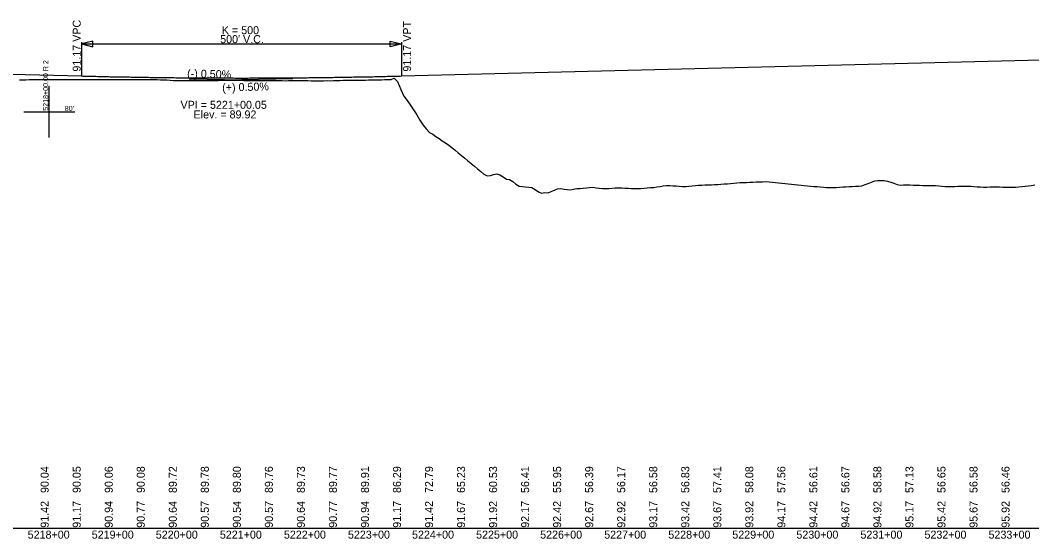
# Model space of a CAD drawing. Extents: x 2147288 to 2220488, y 740833 to 759333.
# Drawn here: x 2154136 to 2155715, y 742067 to 742876 of the extents above; entities that cross this region are included whole.
import ezdxf

# ---------------------------------------------------------------- set-up
doc = ezdxf.new("R2010")
doc.units = 0
for name, color, linetype in [('RD_DDB_GradeTX', 7, 'Continuous'), ('RD_DDB_Profile_EX', 7, 'Continuous'), ('RD_DDB_Profile_Lbl', 7, 'Continuous'), ('RD_DDB_Profile_PR', 7, 'Continuous'), ('RD_DDB_StaTX', 7, 'Continuous'), ('RD_DDB_StripGrade', 7, 'Continuous'), ('RD_DDB_VCLbl', 7, 'Continuous'), ('RD_GPK_Profile_Cell', 7, 'Continuous')]:
    doc.layers.add(name, color=color, linetype=linetype)

msp = doc.modelspace()

# ---------------------------------------------------------------- linework, layer by layer
at = {"layer": 'RD_DDB_GradeTX'}
for p in [(2154401.2, 742785), (2154561.1, 742785)]:
    msp.add_line(p, (2154481.1, 742783), dxfattribs=at)
at = {"layer": 'RD_DDB_Profile_EX'}
for points in [[(2154134.6, 742783.5), (2154139.6, 742783.5), (2154144.6, 742783.5), (2154149.6, 742783.6), (2154154.6, 742783.6), (2154159.6, 742783.6), (2154164.6, 742783.6), (2154169.6, 742783.6), (2154174.6, 742783.6), (2154179.6, 742783.6), (2154184.6, 742783.6), (2154189.6, 742783.6), (2154194.6, 742783.6), (2154199.6, 742783.6), (2154204.6, 742783.7), (2154209.6, 742783.7), (2154214.6, 742783.7), (2154219.6, 742783.7), (2154224.6, 742783.7), (2154229.6, 742783.7), (2154234.6, 742783.7), (2154239.6, 742783.7), (2154244.6, 742783.7), (2154249.6, 742783.8), (2154254.6, 742783.8), (2154259.6, 742783.8), (2154264.6, 742783.8), (2154269.6, 742783.8), (2154274.6, 742783.7), (2154279.6, 742783.7), (2154284.6, 742783.7), (2154289.6, 742783.7), (2154294.6, 742783.8), (2154299.6, 742783.8), (2154304.6, 742783.8), (2154309.6, 742783.8), (2154314.6, 742783.8), (2154319.6, 742783.9), (2154324.6, 742783.8), (2154329.6, 742783.8), (2154334.6, 742783.8), (2154339.6, 742783.9), (2154344.6, 742783.9), (2154349.6, 742783.9), (2154354.6, 742783.2), (2154359.6, 742783.2), (2154364.6, 742783), (2154369.6, 742782.7), (2154374.6, 742782.4), (2154379.6, 742782), (2154384.6, 742782.1), (2154389.6, 742782.1), (2154394.6, 742782), (2154399.6, 742782), (2154404.6, 742782.1), (2154409.6, 742782.1), (2154414.6, 742782.1), (2154419.6, 742782.1), (2154424.6, 742782.3), (2154429.6, 742782.3), (2154434.6, 742782.3), (2154439.6, 742782.3), (2154444.6, 742782.4), (2154449.6, 742782.5), (2154454.6, 742782.6), (2154459.6, 742782.7), (2154464.6, 742782.7), (2154469.6, 742782.6), (2154474.6, 742782.6), (2154479.6, 742782.5), (2154484.6, 742782.4), (2154489.6, 742782.3), (2154494.6, 742782.3), (2154499.6, 742782.3), (2154504.6, 742782.3), (2154509.6, 742782.3), (2154514.6, 742782.2), (2154519.6, 742782.2), (2154524.6, 742782.2), (2154529.6, 742782.2), (2154534.6, 742782.3)], [(2154534.6, 742782.3), (2154539.6, 742782.2), (2154544.6, 742782), (2154549.6, 742781.9), (2154554.6, 742782), (2154559.6, 742782.1), (2154564.6, 742782), (2154569.6, 742782), (2154574.6, 742782), (2154579.6, 742782.1), (2154584.6, 742782), (2154589.6, 742781.9), (2154594.6, 742781.8), (2154599.6, 742781.8), (2154604.6, 742781.9), (2154609.6, 742781.9), (2154614.6, 742782), (2154619.6, 742781.9), (2154624.6, 742782), (2154629.6, 742782.2), (2154634.6, 742782.4), (2154639.6, 742782.6), (2154644.6, 742782.8), (2154649.6, 742782.9), (2154654.6, 742782.9), (2154659.6, 742782.9), (2154664.6, 742782.9), (2154669.6, 742782.9), (2154674.6, 742782.9), (2154679.6, 742783), (2154684.6, 742783), (2154689.6, 742783), (2154694.6, 742783.1), (2154699.6, 742783.3), (2154704.6, 742783.6), (2154709.6, 742783.7), (2154714.6, 742783.9), (2154719.6, 742786), (2154724.6, 742780.7), (2154729.6, 742768), (2154734.6, 742757.6), (2154739.6, 742750.9), (2154744.6, 742744.1), (2154749.6, 742736.5), (2154754.6, 742728.5), (2154759.6, 742720.5), (2154764.6, 742712.5), (2154769.6, 742706.6), (2154774.6, 742700.9), (2154779.6, 742698.4), (2154784.6, 742695), (2154789.6, 742691.6), (2154794.6, 742688.3), (2154799.6, 742684.9), (2154804.6, 742681.5), (2154809.6, 742677.4), (2154814.6, 742673.3), (2154819.6, 742669.1), (2154824.6, 742665), (2154829.6, 742660.8), (2154834.6, 742656.7), (2154839.6, 742652.6), (2154844.6, 742648.4), (2154849.6, 742644.3), (2154854.6, 742640.1), (2154859.6, 742636), (2154864.6, 742633.5), (2154869.6, 742633.9), (2154874.6, 742635.5), (2154879.6, 742636.5), (2154884.6, 742635.2), (2154889.6, 742631.7), (2154894.6, 742628.3), (2154899.6, 742627.6), (2154904.6, 742624.5), (2154909.6, 742620.5), (2154914.6, 742617.3), (2154919.6, 742616.6), (2154924.6, 742616), (2154929.6, 742615.6), (2154934.6, 742615.1), (2154939.6, 742611.9), (2154944.6, 742608.6), (2154949.6, 742606.6), (2154954.6, 742607.2), (2154959.6, 742606.9), (2154964.6, 742608.9), (2154969.6, 742611.1), (2154974.6, 742613.1), (2154979.6, 742613.4), (2154984.6, 742612.7), (2154989.6, 742611.9), (2154994.6, 742611.8), (2154999.6, 742612.7), (2155004.6, 742613.5), (2155009.6, 742613.8), (2155014.6, 742614.4), (2155019.6, 742614.9), (2155024.6, 742615.4), (2155029.6, 742615.6), (2155034.6, 742614.9)], [(2155034.6, 742614.9), (2155039.6, 742614.2), (2155044.6, 742613.6), (2155049.6, 742613.7), (2155054.6, 742613.9), (2155059.6, 742614.2), (2155064.6, 742614.5), (2155069.6, 742614.6), (2155074.6, 742614.6), (2155079.6, 742614.4), (2155084.6, 742614.1), (2155089.6, 742613.9), (2155094.6, 742613.8), (2155099.6, 742613.6), (2155104.6, 742613.9), (2155109.6, 742614.3), (2155114.6, 742614.7), (2155119.6, 742615), (2155124.6, 742615.3), (2155129.6, 742616.1), (2155134.6, 742616.9), (2155139.6, 742617.7), (2155144.6, 742618.2), (2155149.6, 742618.4), (2155154.6, 742618), (2155159.6, 742617.6), (2155164.6, 742617.3), (2155169.6, 742617), (2155174.6, 742617), (2155179.6, 742617.4), (2155184.6, 742617.9), (2155189.6, 742618.4), (2155194.6, 742618.8), (2155199.6, 742619), (2155204.6, 742619.2), (2155209.6, 742619.3), (2155214.6, 742619.6), (2155219.6, 742619.8), (2155224.6, 742620.1), (2155229.6, 742620.4), (2155234.6, 742620.7), (2155239.6, 742620.9), (2155244.6, 742621.3), (2155249.6, 742621.8), (2155254.6, 742622.3), (2155259.6, 742622.8), (2155264.6, 742623), (2155269.6, 742623.2), (2155274.6, 742623.5), (2155279.6, 742623.8), (2155284.6, 742624), (2155289.6, 742624.1), (2155294.6, 742624.3), (2155299.6, 742624.4), (2155304.6, 742624.3), (2155309.6, 742623.7), (2155314.6, 742623), (2155319.6, 742622.4), (2155324.6, 742621.9), (2155329.6, 742621.4), (2155334.6, 742620.9), (2155339.6, 742620.4), (2155344.6, 742619.9), (2155349.6, 742619.4), (2155354.6, 742618.9), (2155359.6, 742618.4), (2155364.6, 742617.9), (2155369.6, 742617.5), (2155374.6, 742617), (2155379.6, 742616.6), (2155384.6, 742616.2), (2155389.6, 742615.8), (2155394.6, 742615.4), (2155399.6, 742615.1), (2155404.6, 742615.2), (2155409.6, 742615.4), (2155414.6, 742615.6), (2155419.6, 742616), (2155424.6, 742616.3), (2155429.6, 742616.7), (2155434.6, 742617), (2155439.6, 742617.2), (2155444.6, 742617.4), (2155449.6, 742617.8), (2155454.6, 742619.7), (2155459.6, 742621.6), (2155464.6, 742623.6), (2155469.6, 742625.5), (2155474.6, 742626.2), (2155479.6, 742626.3), (2155484.6, 742626.4), (2155489.6, 742625.2), (2155494.6, 742623.5), (2155499.6, 742621.8), (2155504.6, 742620.1), (2155509.6, 742619.1), (2155514.6, 742619.2), (2155519.6, 742619.4), (2155524.6, 742619.4), (2155529.6, 742619.1), (2155534.6, 742618.9)], [(2155534.6, 742618.9), (2155539.6, 742618.6), (2155544.6, 742618.4), (2155549.6, 742618.3), (2155554.6, 742618.2), (2155559.6, 742618.1), (2155564.6, 742618.1), (2155569.6, 742617.7), (2155574.6, 742617.2), (2155579.6, 742616.7), (2155584.6, 742616.6), (2155589.6, 742616.8), (2155594.6, 742616.9), (2155599.6, 742617.1), (2155604.6, 742617.2), (2155609.6, 742617.3), (2155614.6, 742617.4), (2155619.6, 742617.4), (2155624.6, 742616.9), (2155629.6, 742616.5), (2155634.6, 742616), (2155639.6, 742615.6), (2155644.6, 742615.7), (2155649.6, 742616), (2155654.6, 742616.2), (2155659.6, 742616.1), (2155664.6, 742616), (2155669.6, 742615.9), (2155674.6, 742615.8), (2155679.6, 742615.8), (2155684.6, 742615.7), (2155689.6, 742615.6), (2155694.6, 742616), (2155699.6, 742616.6), (2155704.6, 742617.2), (2155709.6, 742617.8), (2155714.6, 742618.5), (2155719.6, 742619.4)]]:
    msp.add_lwpolyline(points, dxfattribs=at)
at = {"layer": 'RD_DDB_Profile_PR'}
for p, q in [((2154731.1, 742789.3), (2156331.1, 742829.3)), ((2154061.1, 742793.5), (2154231.1, 742789.3))]:
    msp.add_line(p, q, dxfattribs=at)
msp.add_spline([(2154231.1, 742789.3), (2154241.1, 742789), (2154251.1, 742788.8), (2154261.1, 742788.6), (2154271.1, 742788.3), (2154281.1, 742788.1), (2154291.1, 742787.9), (2154301.1, 742787.8), (2154311.1, 742787.6), (2154321.1, 742787.4), (2154331.1, 742787.3), (2154341.1, 742787.1), (2154351.1, 742787), (2154361.1, 742786.9), (2154371.1, 742786.7), (2154381.1, 742786.6), (2154391.1, 742786.5), (2154401.1, 742786.5), (2154411.1, 742786.4), (2154421.1, 742786.3), (2154431.1, 742786.3), (2154441.1, 742786.2), (2154451.1, 742786.2), (2154461.1, 742786.2), (2154471.1, 742786.1), (2154481.1, 742786.1), (2154491.1, 742786.1), (2154501.1, 742786.2), (2154511.1, 742786.2), (2154521.1, 742786.2), (2154531.1, 742786.3), (2154541.1, 742786.3), (2154551.1, 742786.4), (2154561.1, 742786.5), (2154571.1, 742786.5), (2154581.1, 742786.6), (2154591.1, 742786.7), (2154601.1, 742786.9), (2154611.1, 742787), (2154621.1, 742787.1), (2154631.1, 742787.3), (2154641.1, 742787.4), (2154651.1, 742787.6), (2154661.1, 742787.8), (2154671.1, 742787.9), (2154681.1, 742788.1), (2154691.1, 742788.3), (2154701.1, 742788.6), (2154711.1, 742788.8), (2154721.1, 742789), (2154731.1, 742789.3)], degree=3, dxfattribs=at)
at = {"layer": 'RD_DDB_VCLbl'}
for p, q in [((2154231.1, 742841.8), (2154231.1, 742789.3)), ((2154231.1, 742839.3), (2154731.1, 742839.3)), ((2154731.1, 742841.8), (2154731.1, 742789.3))]:
    msp.add_line(p, q, dxfattribs=at)
for points in [[(2154249.1, 742843.8), (2154231.1, 742839.3), (2154249.1, 742834.8)], [(2154713.1, 742843.8), (2154731.1, 742839.3), (2154713.1, 742834.8)]]:
    msp.add_lwpolyline(points, close=True, dxfattribs=at)
at = {"layer": 'RD_GPK_Profile_Cell'}
for p, q in [((2154181.1, 742693.4), (2154181.1, 742773.4)), ((2154141.1, 742733.4), (2154221.1, 742733.4)), ((2148888.3, 742083.4), (2165888.3, 742083.4))]:
    msp.add_line(p, q, dxfattribs=at)

# ---------------------------------------------------------------- texts
at = {"layer": 'RD_DDB_GradeTX'}
for s, rotation, p in [('(-) 0.50%', 358.5679, (2154396.1, 742787.1)), ('(+) 0.50%', 1.4321, (2154451.1, 742765))]:
    msp.add_text(s, height=12.5, rotation=rotation, dxfattribs=at).set_placement(p)
at = {"layer": 'RD_DDB_Profile_Lbl'}
for s, p in [('VPI = 5221+00.05', (2154385.9, 742738)), ('Elev. = 89.92', (2154406.3, 742723))]:
    msp.add_text(s, height=12.5, dxfattribs=at).set_placement(p)
at = {"layer": 'RD_DDB_StaTX'}
for s, p in [('5218+00', (2154147.3, 742067.2)), ('5219+00', (2154247.3, 742067.2)), ('5220+00', (2154347.3, 742067.2)), ('5221+00', (2154447.3, 742067.2)), ('5222+00', (2154547.3, 742067.2)), ('5223+00', (2154647.3, 742067.2)), ('5224+00', (2154747.3, 742067.2)), ('5225+00', (2154847.3, 742067.2)), ('5226+00', (2154947.3, 742067.2)), ('5227+00', (2155047.3, 742067.2)), ('5228+00', (2155147.3, 742067.2)), ('5229+00', (2155247.3, 742067.2)), ('5230+00', (2155347.3, 742067.2)), ('5231+00', (2155447.3, 742067.2)), ('5232+00', (2155547.3, 742067.2)), ('5233+00', (2155647.3, 742067.2))]:
    msp.add_text(s, height=12.5, dxfattribs=at).set_placement(p)
at = {"layer": 'RD_DDB_StripGrade'}
for s, p in [('91.17 VPC', (2154230.1, 742796.1)), ('91.17 VPT', (2154745.8, 742796.1)), ('90.04', (2154180.1, 742138.4)), ('90.05', (2154230.1, 742138.4)), ('90.06', (2154280.1, 742138.4)), ('90.08', (2154330.1, 742138.4)), ('89.72', (2154380.1, 742138.4)), ('89.78', (2154430.1, 742138.4)), ('89.80', (2154480.1, 742138.4)), ('89.76', (2154530.1, 742138.4)), ('89.73', (2154580.1, 742138.4)), ('89.77', (2154630.1, 742138.4)), ('89.91', (2154680.1, 742138.4)), ('86.29', (2154730.1, 742138.4)), ('72.79', (2154780.1, 742138.4)), ('65.23', (2154830.1, 742138.4)), ('60.53', (2154880.1, 742138.4)), ('56.41', (2154930.1, 742138.4)), ('55.95', (2154980.1, 742138.4)), ('56.39', (2155030.1, 742138.4)), ('56.17', (2155080.1, 742138.4)), ('56.58', (2155130.1, 742138.4)), ('56.83', (2155180.1, 742138.4)), ('57.41', (2155230.1, 742138.4)), ('58.08', (2155280.1, 742138.4)), ('57.56', (2155330.1, 742138.4)), ('56.61', (2155380.1, 742138.4)), ('56.67', (2155430.1, 742138.4)), ('58.58', (2155480.1, 742138.4)), ('57.13', (2155530.1, 742138.4)), ('56.65', (2155580.1, 742138.4)), ('56.58', (2155630.1, 742138.4)), ('56.46', (2155680.1, 742138.4)), ('91.42', (2154180.1, 742084.2)), ('91.17', (2154230.1, 742084.2)), ('90.94', (2154280.1, 742084.2)), ('90.77', (2154330.1, 742084.2)), ('90.64', (2154380.1, 742084.2)), ('90.57', (2154430.1, 742084.2)), ('90.54', (2154480.1, 742084.2)), ('90.57', (2154530.1, 742084.2)), ('90.64', (2154580.1, 742084.2)), ('90.77', (2154630.1, 742084.2)), ('90.94', (2154680.1, 742084.2)), ('91.17', (2154730.1, 742084.2)), ('91.42', (2154780.1, 742084.2)), ('91.67', (2154830.1, 742084.2)), ('91.92', (2154880.1, 742084.2)), ('92.17', (2154930.1, 742084.2)), ('92.42', (2154980.1, 742084.2)), ('92.67', (2155030.1, 742084.2)), ('92.92', (2155080.1, 742084.2)), ('93.17', (2155130.1, 742084.2)), ('93.42', (2155180.1, 742084.2)), ('93.67', (2155230.1, 742084.2)), ('93.92', (2155280.1, 742084.2)), ('94.17', (2155330.1, 742084.2)), ('94.42', (2155380.1, 742084.2)), ('94.67', (2155430.1, 742084.2)), ('94.92', (2155480.1, 742084.2)), ('95.17', (2155530.1, 742084.2)), ('95.42', (2155580.1, 742084.2)), ('95.67', (2155630.1, 742084.2)), ('95.92', (2155680.1, 742084.2))]:
    msp.add_text(s, height=12.5, rotation=90, dxfattribs=at).set_placement(p)
at = {"layer": 'RD_DDB_VCLbl'}
for s, p in [('K = 500', (2154450.4, 742854.5)), ("500' V.C.", (2154447.8, 742840.5))]:
    msp.add_text(s, height=12.5, dxfattribs=at).set_placement(p)
at = {"layer": 'RD_GPK_Profile_Cell'}
msp.add_text('5218+00.00 R 2', height=8, rotation=90, dxfattribs=at).set_placement((2154179.3, 742735))
msp.add_text("80'", height=8, dxfattribs=at).set_placement((2154205.2, 742734.6))

doc.saveas('drawing.dxf')
